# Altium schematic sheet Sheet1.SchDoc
size A
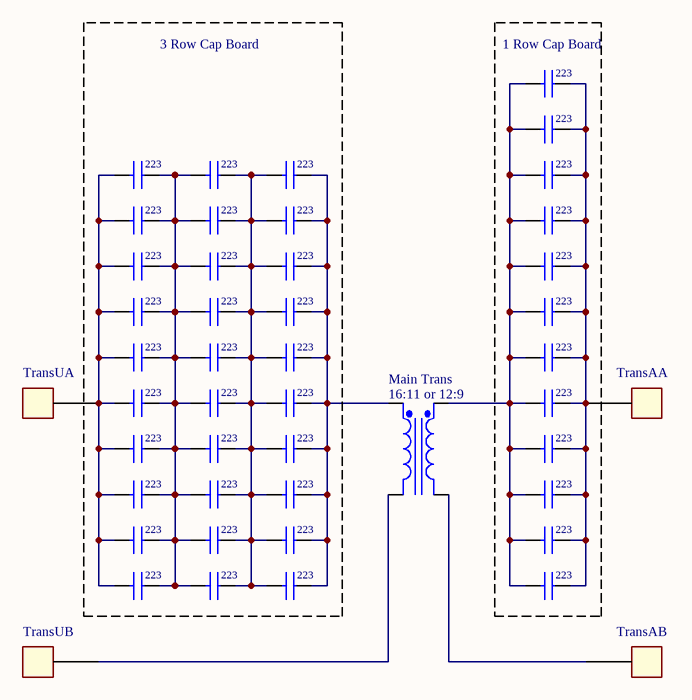
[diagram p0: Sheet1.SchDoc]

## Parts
C1  223  [SMT_1210]
C2  223  [SMT_1210]
C3  223  [SMT_1210]
C4  223  [SMT_1210]
C5  223  [SMT_1210]
C6  223  [SMT_1210]
C7  223  [SMT_1210]
C8  223  [SMT_1210]
C9  223  [SMT_1210]
C10  223  [SMT_1210]
C11  223  [SMT_1210]
C12  223  [SMT_1210]
C13  223  [SMT_1210]
C14  223  [SMT_1210]
C15  223  [SMT_1210]
C16  223  [SMT_1210]
C17  223  [SMT_1210]
C18  223  [SMT_1210]
C19  223  [SMT_1210]
C20  223  [SMT_1210]
C21  223  [SMT_1210]
C22  223  [SMT_1210]
C23  223  [SMT_1210]
C24  223  [SMT_1210]
C25  223  [SMT_1210]
C26  223  [SMT_1210]
C27  223  [SMT_1210]
C28  223  [SMT_1210]
C29  223  [SMT_1210]
C30  223  [SMT_1210]
C50  223  [SMT_1210]
C51  223  [SMT_1210]
C52  223  [SMT_1210]
C53  223  [SMT_1210]
C54  223  [SMT_1210]
C55  223  [SMT_1210]
C56  223  [SMT_1210]
C57  223  [SMT_1210]
C58  223  [SMT_1210]
C59  223  [SMT_1210]
C111  223  [SMT_1210]
C?  223  [SMT_1210]
Main_Trans  16:11 or 12:9  [TRF_4]
TransAA  (no value)  [TermL]
TransAB  (no value)  [TermL]
TransUA  (no value)  [TermL]
TransUB  (no value)  [TermL]

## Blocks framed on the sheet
3 Row Cap Board: C1-C30
1 Row Cap Board: C50-C59 C111 C?

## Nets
NetC1_1: C1.1 C2.2 C4.1 C5.2 C7.1 C8.2 C10.1 C11.2 C13.1 C14.2 C16.1 C17.2 C19.1 C20.2 C22.1 C23.2 C25.1 C26.2 C28.1 C29.2
NetC1_2: C1.2 C4.2 C7.2 C10.2 C13.2 C16.2 C19.2 C22.2 C25.2 C28.2 TransUA.1
NetC2_1: C2.1 C3.2 C5.1 C6.2 C8.1 C9.2 C11.1 C12.2 C14.1 C15.2 C17.1 C18.2 C20.1 C21.2 C23.1 C24.2 C26.1 C27.2 C29.1 C30.2
NetC3_1: C3.1 C6.1 C9.1 C12.1 C15.1 C18.1 C21.1 C24.1 C27.1 C30.1 Main_Trans.1(Pri+)
NetC50_1: C50.1 C51.1 C52.1 C53.1 C54.1 C55.1 C56.1 C57.1 C58.1 C59.1 C111.1 C?.1 TransAA.1
NetC50_2: C50.2 C51.2 C52.2 C53.2 C54.2 C55.2 C56.2 C57.2 C58.2 C59.2 C111.2 C?.2 Main_Trans.3(Sec+)
NetMain_Trans_2: Main_Trans.2(Pri-) TransUB.1
NetMain_Trans_4: Main_Trans.4(Sec-) TransAB.1

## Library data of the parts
C1-C30 C50-C59 C111 C? = CAP NP
Main_Trans = Trans Ideal: Transformer (Ideal)
TransAA TransAB TransUA TransUB = P_1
